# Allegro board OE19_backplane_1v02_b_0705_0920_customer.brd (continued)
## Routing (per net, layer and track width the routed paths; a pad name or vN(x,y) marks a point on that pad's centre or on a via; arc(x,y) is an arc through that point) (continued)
FM_BMC_SLED3_READY_N: length 72.1
  TOP w0.114: v1(203.01,30.38) 203.01,30.38 199.68,33.71 193.08,36.44 187.07,36.44 185.84,35.21 185.84,26.29 J8.F8
  IN1 w0.127: v1(203.01,30.38) 205.21,32.58 213.16,32.58 214.76,30.98 215.9,30.98 v1(216.16,31.24)
  BOTTOM w0.114: J10.H3 225.7,52.75 225.7,43.67 216.16,34.12 v1(216.16,31.24)
FM_BMC_SLED4_READY_N: length 225.1
  TOP w0.114: v1(31.77,68.45) 31.17,67.85 31.17,44.98 37.68,38.47 175.37,38.47 175.98,37.86 175.98,33.25 J8.K3
  BOTTOM w0.114: J11.H3 8.24,95.56 8.24,76.65 15.57,69.32 30.9,69.32 v1(31.77,68.45)
FM_BMC_SLED5_READY_N: length 109.6
  TOP w0.114: J12.H3 225.61,95.51 225.61,77.27 216.34,68 216.34,32.47 v1(215.32,31.45) ; v1(202.11,30.48) 201.79,30.8 201.79,31.23 199.53,33.48 193.02,36.18 187.18,36.18 186.11,35.1 186.11,30.23 J8.I8
  IN1 w0.127: v1(215.32,31.45) 214.95,31.45 213.36,33.05 204.68,33.05 v1(202.11,30.48)
FM_RMC_GPIO_0: length 450.7
  TOP w0.114: J9.D3 8.12,49.57 8.12,57.42 11.91,61.21 11.91,66.98 v1(13.87,68.94) ; v1(216.85,30.61) 216.85,68.12 225.88,77.16 225.88,90.18 J12.D3 ; J7.D3 226.02,6.48 226.02,9.93 225.56,10.38 225.56,12.7 225.15,13.11 224.35,13.11 216.84,20.62 v1(216.84,25.11) ; v1(226.77,75.2) 226.77,71.59 231.89,66.46 231.89,60.24 228.14,56.48 228.14,49.59 J10.D3 ; v1(204.43,31.12) 204.43,31.13 201.84,33.72 193.25,37.28 185.14,37.28 v1(184.91,37.05) 184.32,37.05 183.73,36.46 183.73,26.06 J8.F6
  IN1 w0.127: v1(204.43,31.12) 205.55,32.25 212.71,32.25 214.35,30.61 v1(216.85,30.61) ; v1(32.86,33.61) 32.86,34.02 37.35,38.52 179.56,38.52 181.02,37.05 v1(184.91,37.05)
  BOTTOM w0.114: J11.D3 7.8,90.4 7.8,74.39 10.37,71.83 10.97,71.83 v1(13.87,68.94) ; J9.D3 7.31,48.4 7.83,47.88 7.83,43.7 9.41,42.12 15.42,42.12 17.89,39.65 25.72,39.65 31.76,33.61 v1(32.86,33.61) ; v1(216.84,25.11) 216.84,26.2 217.62,26.98 217.62,34.61 226.24,43.23 226.24,47.69 J10.D3 ; J12.D3 226.97,91.25 227.91,90.32 227.91,84.22 226.9,83.22 226.9,75.33 v1(226.77,75.2)
FM_RMC_GPIO_1: length 388.3
  TOP w0.114: v1(6.19,56.37) 6.19,50.56 J9.E3 ; J7.E3 226.29,7.61 226.29,10.04 225.83,10.49 225.83,12.81 225.26,13.38 224.46,13.38 217.11,20.73 217.11,23.38 v1(218.18,24.44) ; J8.H6 181.75,29.19 181.75,30.21 181.74,30.22 181.74,34.15 v1(180.92,34.97) 180.61,35.28 180.61,35.9 181.28,36.56 182.62,36.56 183.87,37.82 193.35,37.82 202.6,33.99 205.98,30.61 205.98,30.34 v1(206.3,30.01) ; v1(226.3,74.77) 226.3,71.56 231.63,66.23 231.63,60.47 227.84,56.68 227.84,50.69 J10.E3
  IN1 w0.127: v1(206.3,30.01) 207.04,29.27 212.78,29.27 214.89,27.16 215.46,27.16 v1(218.18,24.44) ; v1(180.92,34.97) 180.61,35.29 180.61,35.78 179.08,37.3 38.22,37.3 34.67,33.75 v1(34.67,33.64)
  BOTTOM w0.114: J9.E3 8.1,48.65 8.1,43.93 9.58,42.44 15.62,42.44 18.15,39.91 25.94,39.91 31.74,34.11 34.2,34.11 v1(34.67,33.64) ; J12.E3 226.55,92.65 226.13,92.23 226.13,74.94 v1(226.3,74.77) ; v1(218.18,24.44) 219.17,25.43 219.17,34.21 228.05,43.1 228.05,48.7 J10.E3 ; v1(6.19,56.37) 6.19,56.99 6.86,57.66 8.19,57.66 8.4,57.74 13.18,62.53 13.18,67.45 6.31,74.32 6.31,92.01 J11.E3
FM_RMC_GPIO_2: length 391.6
  TOP w0.114: v1(7.86,58.12) 7.86,53.51 J9.G3 ; J10.G3 227.57,53.22 227.57,56.79 231.36,60.58 231.36,66.12 225.83,71.65 225.83,75.55 227.29,77.01 227.29,82.1 227.83,82.64 227.83,94.57 J12.G3 ; J7.G3 226.1,10.6 226.1,12.93 225.37,13.65 224.57,13.65 217.58,20.65 v1(217.58,23.11) ; v1(205.62,30.03) 205.34,30.32 205.34,30.87 202.44,33.76 193.3,37.55 183.98,37.55 182.73,36.3 181.39,36.3 181.11,36.02 v1(181.11,35.74) 181.11,35.44 182.01,34.54 182.01,30.33 J8.I6
  IN1 w0.127: v1(181.11,35.74) 179.22,37.63 164.55,37.63 164.53,37.65 38.01,37.65 34.14,33.78 v1(34.14,32.58) ; v1(217.58,23.11) 217.58,23.64 212.96,28.26 209.55,28.26 208.86,28.94 206.7,28.94 205.62,30.02 v1(205.62,30.03)
  BOTTOM w0.114: v1(217.58,23.11) 216.26,24.43 216.26,25.98 217.36,27.09 217.36,34.82 225.97,43.43 225.97,51.62 J10.G3 ; J9.G3 6.55,52.6 6.29,52.33 6.29,43.65 9.48,40.46 15,40.46 17.15,38.31 25.29,38.31 31.48,32.12 33.68,32.12 v1(34.14,32.58) ; J11.G3 6.05,94.55 6.05,74.21 12.23,68.03 12.23,61.95 8.78,58.51 v1(7.86,58.12)
FM_SLED1_PRSNT_N: length 85.8
  TOP w0.114: J7.B3 227.83,3.63 227.83,12.91 226.56,14.18 224.79,14.18 218.48,20.5 218.48,23.31 218.91,23.73 218.91,24.75 217.17,26.48 212.83,26.48 212.62,26.7 v1(212.37,26.7) R36.2
  IN1 w0.127: J8.B8 188.09,20.83 188.09,34.81 188.94,35.66 191.31,35.66 195.3,31.67 195.3,28.18 198.47,25.01 213.11,25.01 213.36,25.26 213.36,25.96 212.62,26.7 v1(212.37,26.7)
FM_SLED2_PRSNT_N: length 217.2
  TOP w0.114: J8.G3 177.78,27.61 177.78,34.45 v1(176.73,35.49) 176.73,36.48 177.98,37.73 181.65,37.73 v1(182.15,38.23) ; R35.2 199.91,29.79 199.04,30.65 v1(199.04,31.27)
  IN1 w0.127: v1(36.17,32.66) 36.17,33.17 39.01,36.01 176.32,36.01 176.73,35.59 v1(176.73,35.49) ; v1(199.04,31.27) 199.04,31.92 192.48,38.48 182.41,38.48 v1(182.15,38.23)
  BOTTOM w0.114: v1(36.17,32.66) 35.59,32.66 35.16,33.09 31.71,33.09 25.41,39.38 17.54,39.38 15.39,41.53 9.62,41.53 7.56,43.59 7.56,44.94 6.95,45.55 J9.B3
FM_SLED3_PRSNT_N: length 62.7
  TOP w0.114: J8.E8 186.9,24.3 187.58,24.98 187.58,26.53 188,26.95 188,33.7 189.95,35.64 192.92,35.64 197.63,33.69 200.06,31.26 v1(200.06,30.47) 200.92,29.61 R34.2
  IN1 w0.127: v1(218.57,33.71) 203.3,33.71 v1(200.06,30.47)
  BOTTOM w0.114: J10.B3 227.79,44.76 227.79,43.5 218.57,34.28 v1(218.57,33.71)
FM_SLED4_PRSNT_N: length 255.9
  TOP w0.114: v1(11,58.39) 11.94,57.45 11.94,43.11 v1(12.13,42.92) ; J8.J3 177.51,31.54 177.51,34.05 v1(176.97,34.59) 176.27,35.29 176.27,36.39 178.12,38.25 v1(181.34,38.25) ; v1(198.07,30.21) 198.33,30.21 198.89,29.65 R33.2
  IN1 w0.127: v1(176.97,34.59) 175.93,35.63 39.16,35.63 37.48,33.94 37.48,33.4 v1(37.32,33.24) ; v1(181.34,38.25) 181.83,37.76 182.46,37.76 182.85,38.15 192.34,38.15 198.07,32.43 v1(198.07,30.21)
  BOTTOM w0.114: v1(37.32,33.24) 35.92,33.24 34.7,34.46 31.85,34.46 26,40.31 18.43,40.31 15.83,42.92 v1(12.13,42.92) ; v1(11,58.39) 11,59.16 14.09,62.25 14.09,67.73 7.54,74.28 7.54,87.86 J11.B3
FM_SLED5_PRSNT_N: length 103.4
  TOP w0.114: R30.2 201.94,29.59 v1(201.08,30.45) 201.08,31.24 198.84,33.48 192.97,35.91 189.84,35.91 187.73,33.81 187.73,28.87 J8.H8 ; v1(218.63,32.76) 217.68,33.7 217.68,67.78 227.03,77.12 227.03,82.21 227.56,82.75 227.56,87.84 J12.B3
  IN1 w0.127: v1(218.63,32.76) 218.01,33.38 204,33.38 v1(201.08,30.45)
IRQ_RMC_ALERT_N: length 400.7
  TOP w0.114: J8.E6 184.15,25.08 184.15,36.23 v1(184.45,36.53) 185.33,36.53 185.66,36.86 193.16,36.86 201.53,33.4 204.02,30.91 v1(204.02,30.45) ; v1(6.85,57) 6.17,57 5.73,56.56 5.73,45.42 J9.A3 ; J7.A3 228.25,2.65 228.25,13.09 226.74,14.6 224.97,14.6 218.94,20.63 v1(218.94,22.71) ; J12.A3 226.61,86.71 226.61,77.29 217.26,67.95 217.26,32.29 218.09,31.47 v1(218.09,30.96)
  IN1 w0.127: v1(204.02,30.45) 204.97,30.45 205.88,31.35 212.99,31.35 214.21,30.14 217.26,30.14 v1(218.09,30.96) ; v1(184.45,36.53) 180.93,36.53 179.38,38.09 37.69,38.09 33.47,33.87 v1(33.47,32.61)
  BOTTOM w0.114: J10.A3 226.95,43.33 218.09,34.47 v1(218.09,30.96) 218.04,30.92 218.04,26.7 217.45,26.11 217.45,24.21 v1(218.94,22.71) ; v1(6.85,57) 7.07,57.21 8.2,57.21 8.63,57.39 13.64,62.39 13.64,67.59 6.95,74.28 J11.A3 ; v1(33.47,32.61) 31.59,32.61 25.43,38.77 17.44,38.77 15.14,41.07 9.48,41.07 6.95,43.6 J9.A3
LAN_SLED1_MDIN0: length 53
  IN2 w0.114: J8.C10 191.39,20.55 196.73,20.55 205.38,20.36 217.8,15.19 227.62,15 229.06,14.38 230.16,13.28 230.16,2.4 230.3,2.26 230.46,2.26 J7.B1
LAN_SLED1_MDIN1: length 53.7
  IN2 w0.114: J7.E1 231.44,6.46 232.05,6.46 232.26,6.55 232.31,6.6 232.46,6.95 232.49,7.94 232.3,8.13 232.31,8.48 232.5,8.66 232.51,9 232.33,9.2 232.34,9.54 232.53,9.72 232.54,10.07 232.36,10.26 232.36,10.6 232.56,10.79 232.57,11.13 232.38,11.32 232.39,11.67 232.58,11.85 232.59,12.24 232.59,12.79 232.37,13.14 232.02,13.2 231.83,13.49 231.9,13.83 231.53,14.39 231,14.61 230.69,14.48 230.37,14.61 230.25,14.92 227.88,15.9 220.35,15.97 218.06,16.91 217.74,16.77 217.42,16.91 217.28,17.23 216.97,17.37 216.64,17.23 216.32,17.36 216.18,17.69 206.67,21.63 193.13,24.32 191.39,24.32 J8.E10
LAN_SLED1_MDIN2: length 47.1
  BOTTOM w0.099: J8.B9 189.42,19.21 189.73,19.21 190.08,18.86 190.08,17.98 190.12,17.87 190.27,17.72 190.43,17.65 192.12,17.65 194.52,18.65 205.17,18.82 228.81,14.12 229.54,13.82 229.88,13.48 230.13,12.88 230.13,10.79 230.29,10.63 230.43,10.63 J7.H1
LAN_SLED1_MDIN3: length 48.4
  IN2 w0.114: J8.E9 189.39,23.45 189.73,23.45 190.11,23.06 190.11,17.99 190.45,17.65 191.16,17.65 194.22,18.92 195.96,19.25 205.26,19.02 217.85,13.81 219.29,13.81 227.24,13.74 227.78,13.52 228.16,13.14 228.16,12.1 228.3,11.96 228.46,11.96 J7.I2
LAN_SLED1_MDIP0: length 53
  IN2 w0.114: J8.B10 191.39,20.12 196.72,20.12 205.29,19.94 217.71,14.77 227.53,14.57 228.82,14.02 229.74,13.1 229.74,2.22 230.12,1.84 230.46,1.84 J7.A1
LAN_SLED1_MDIP1: length 53.6
  IN2 w0.114: J8.F10 191.39,24.75 193.17,24.75 199.98,23.39 206.79,22.04 220.43,16.39 227.97,16.32 231.81,14.73 233.02,12.92 233.02,12.23 232.89,6.86 232.67,6.36 232.5,6.19 232.14,6.04 231.44,6.04 J7.D1
LAN_SLED1_MDIP2: length 47.1
  BOTTOM w0.099: J8.A9 189.42,18.86 189.58,18.86 189.72,18.72 189.72,17.91 189.82,17.67 190.07,17.42 190.36,17.3 192.19,17.3 194.59,18.29 205.14,18.47 228.71,13.78 229.34,13.52 229.58,13.28 229.77,12.81 229.77,10.64 230.14,10.27 230.43,10.27 J7.G1
LAN_SLED1_MDIP3: length 48.5
  IN2 w0.114: J8.D9 189.39,23.02 189.55,23.02 189.69,22.88 189.69,17.81 190.27,17.22 191.24,17.22 194.35,18.51 195.99,18.82 205.17,18.6 217.76,13.38 219.29,13.38 227.15,13.32 227.54,13.16 227.74,12.96 227.74,11.92 228.12,11.54 228.46,11.54 J7.H2
LAN_SLED2_MDIN0: length 172.5
  BOTTOM w0.099: J9.B1 11.51,45.04 11.97,45.04 14.18,44.83 25.69,41.71 37.21,34.27 41.45,34.39 49.09,33.94 62.97,34.36 65.1,34.21 71.59,34.59 84.85,34.49 99.57,33.55 120.69,34.59 131.16,33.79 140.67,34.61 154.56,33.44 157.52,33.55 160.61,33.67 162.54,32.65 171.68,19.46 172.16,19.21 172.38,19.21 J8.B1
LAN_SLED2_MDIN1: length 172.1
  BOTTOM w0.099: J9.E1 11.47,49.28 11.86,49.28 12.19,49.09 13.21,47.41 13.77,46.75 14.99,45.69 26.01,42.67 37.49,35.26 42.16,35.4 46.1,35.17 58.97,35.56 60.34,35.53 65.11,35.2 71.57,35.58 84.88,35.48 99.58,34.54 120.7,35.57 131.15,34.78 140.67,35.6 154.58,34.42 160.79,34.67 163.12,33.66 169.41,24.6 171.68,23.41 172.38,23.41 J8.E1
LAN_SLED2_MDIN2: length 185.6
  BOTTOM w0.099: J8.C2 174.38,20.51 174.24,20.51 174.08,20.67 174.08,33.93 173.99,34.23 173.46,34.88 172.89,35.18 170.89,35.38 166.25,35.19 162.83,35.73 154.6,35.41 140.67,36.59 131.15,35.77 120.71,36.56 99.58,35.53 84.92,36.46 84.91,36.46 71.56,36.56 71.54,36.56 65.11,36.19 59.64,36.57 46.07,36.16 42.17,36.39 37.76,36.25 26.31,43.65 15.75,46.54 14.13,47.91 12.55,51.27 12.55,52.49 12.28,53.12 11.93,53.48 11.47,53.48 J9.H1
LAN_SLED2_MDIN3: length 202.1
  BOTTOM w0.099: J8.F2 175.42,24.71 175.56,24.71 175.72,24.87 175.72,35.26 175.62,35.71 175.19,36.37 174.4,36.52 174.22,36.4 173.93,36.46 173.81,36.63 173.52,36.69 173.34,36.57 173.05,36.63 172.93,36.8 172.31,36.92 171.67,36.87 171.55,36.74 171.26,36.71 171.12,36.83 170.82,36.81 170.7,36.67 170.4,36.65 170.26,36.77 169.84,36.74 169.71,36.59 169.41,36.57 169.26,36.69 168.96,36.67 168.84,36.52 168.54,36.5 168.39,36.63 168.09,36.61 167.96,36.46 167.67,36.44 167.52,36.56 167.12,36.53 165.45,36.47 165.29,36.29 164.99,36.28 164.82,36.44 164.52,36.43 164.36,36.26 164.06,36.25 163.89,36.41 154.62,36.04 140.67,37.22 131.4,36.43 121.05,37.21 99.59,36.16 95.91,36.39 84.94,37.09 71.53,37.2 65.12,36.82 59.35,37.22 46.21,36.83 42.22,37.06 38.35,37.01 26.21,44.68 23,46.26 22.42,46.95 22.2,47.68 21.97,49.96 22.17,52.27 22.27,58.17 22,59.14 21.13,60.61 20.02,61.3 18.74,61.38 18.58,61.24 18.29,61.26 18.14,61.42 17.85,61.44 17.68,61.3 17.39,61.32 17.25,61.48 16.55,61.53 16.15,61.24 16.12,61.02 15.88,60.85 15.66,60.88 15.42,60.71 15.38,60.49 15.14,60.32 14.92,60.36 14.2,59.84 13.85,59.02 13.36,58.7 13.32,58.48 13.07,58.32 12.85,58.36 12.6,58.2 12.56,57.98 12.31,57.82 12.09,57.86 11.84,57.7 11.79,57.48 11.55,57.31 11.32,57.36 10.99,57.14 10.65,57 10.58,56.83 10.3,56.71 10.13,56.78 9.86,56.67 9.78,56.5 9.51,56.38 9.34,56.45 8.28,56.02 8.13,55.65 8.13,54.94 8.29,54.78 8.43,54.78 J9.I2
LAN_SLED2_MDIP0: length 172.4
  BOTTOM w0.099: J9.A1 11.44,44.69 11.95,44.69 14.11,44.48 25.54,41.38 37.11,33.91 41.44,34.04 49.09,33.59 62.96,34.01 65.1,33.86 71.6,34.24 84.84,34.14 99.57,33.2 120.68,34.23 131.16,33.44 140.67,34.25 147.61,33.67 154.55,33.08 160.52,33.32 162.3,32.38 171.44,19.19 172.07,18.86 172.38,18.86 J8.A1
LAN_SLED2_MDIP1: length 172.1
  BOTTOM w0.099: J8.D1 172.38,23.06 171.59,23.06 169.17,24.33 162.89,33.37 160.72,34.31 154.57,34.07 140.67,35.24 131.15,34.43 120.69,35.22 99.58,34.19 84.87,35.12 71.58,35.23 65.11,34.85 60.32,35.18 58.97,35.2 46.09,34.82 42.15,35.05 37.39,34.9 25.86,42.35 14.82,45.37 13.52,46.5 12.92,47.2 11.94,48.83 11.77,48.92 11.47,48.92 J9.D1
LAN_SLED2_MDIP2: length 185.6
  BOTTOM w0.099: J9.G1 11.47,53.12 11.78,53.12 11.98,52.92 12.19,52.42 12.19,51.19 13.84,47.69 15.59,46.22 26.16,43.33 37.66,35.9 42.17,36.04 46.06,35.81 59.63,36.21 65.11,35.83 71.55,36.21 84.91,36.11 92.23,35.64 99.58,35.17 120.71,36.21 131.15,35.42 131.18,35.42 140.67,36.23 154.59,35.06 162.81,35.38 166.23,34.84 170.88,35.02 172.79,34.84 173.23,34.6 173.67,34.06 173.72,33.88 173.72,20.52 174.09,20.16 174.38,20.16 J8.B2
LAN_SLED2_MDIP3: length 202.2
  BOTTOM w0.099: J8.E2 175.42,24.36 175.71,24.36 176.08,24.72 176.08,35.29 175.95,35.85 175.41,36.69 174.47,36.87 174.47,36.87 172.33,37.28 167.09,36.89 154.62,36.4 140.67,37.58 131.4,36.78 121.06,37.56 99.59,36.51 92.27,36.98 84.95,37.45 78.24,37.5 78.24,37.5 71.52,37.55 65.12,37.18 59.35,37.57 46.22,37.18 42.23,37.41 38.45,37.36 26.39,44.99 23.22,46.55 22.73,47.12 22.55,47.74 22.33,49.96 22.53,52.25 22.63,58.22 22.33,59.28 21.39,60.87 20.13,61.64 16.45,61.89 13.92,60.07 13.81,59.82 13.57,59.26 11.25,57.73 11.25,57.74 10.83,57.46 10.52,57.33 9.2,56.78 9.2,56.78 8.01,56.29 7.77,55.72 7.77,54.79 8.14,54.42 8.43,54.42 J9.H2
LAN_SLED3_MDIN0: length 48.9
  IN2 w0.114: J10.B1 231.44,45.11 232.13,45.11 232.66,44.58 232.66,44 231.74,41.76 231.31,41.34 230.89,40.92 228.04,39.73 221.5,39.23 220.58,38.82 216.4,34.77 213.57,33.58 195.13,33.39 193.73,32.81 191.48,32.81 J8.K10
LAN_SLED3_MDIN1: length 58.6
  IN2 w0.114: J10.E1 231.44,49.31 231.98,49.31 234.43,48.3 235.23,47.5 235.23,43.36 234.96,42.74 231,39.04 228.63,38.15 222.34,38.01 221.07,37.49 217.02,33.64 213.83,32.33 199.18,32.12 196.5,30.99 195.27,29.77 192.18,28.48 191.35,28.48 J8.H10
LAN_SLED3_MDIN2: length 62.9
  IN2 w0.114: J10.H1 230.46,53.51 230.12,53.51 229.74,53.13 229.74,44.02 229.17,42.65 227.49,41.96 224.44,41.68 222.12,41.56 222.01,41.54 221.9,41.51 220.08,40.76 215.3,36.13 213.39,35.33 195.6,35.22 191.32,36.07 190.5,36.07 189.69,35.25 189.69,27.79 189.55,27.65 189.39,27.65 J8.H9
LAN_SLED3_MDIN3: length 60.5
  IN2 w0.114: J10.I2 228.46,54.81 228.12,54.81 227.74,54.43 227.74,44.01 227.12,43.4 225.46,43.24 222.07,42.9 221.89,42.87 219.32,41.8 214.58,37.19 213.1,36.58 195.92,36.76 191.89,37.32 189.99,37.32 188.62,36.75 188.39,36.52 187.69,34.83 187.69,31.81 188.07,31.42 188.41,31.42 J8.J9
LAN_SLED3_MDIP0: length 48.9
  IN2 w0.114: J8.L10 191.3,33.24 191.62,33.24 191.91,33.53 192.23,33.53 192.52,33.24 193.64,33.24 195.05,33.82 213.49,34.01 216.16,35.13 220.34,39.18 221.39,39.65 222.06,39.7 222.33,40.02 222.65,40.04 222.96,39.77 223.28,39.8 223.55,40.11 223.86,40.14 224.17,39.87 224.49,39.89 224.76,40.2 225.08,40.23 225.39,39.96 225.71,39.98 225.98,40.3 226.29,40.32 226.61,40.05 227.94,40.15 230.65,41.28 231.37,42.01 231.63,42.61 231.47,43 231.59,43.29 231.97,43.45 232.24,44.09 232.24,44.4 231.95,44.69 231.44,44.69 J10.A1
LAN_SLED3_MDIP1: length 58.6
  IN2 w0.114: J8.I10 191.42,28.91 192.09,28.91 195.03,30.13 196.26,31.35 199.09,32.55 213.74,32.76 216.79,34 220.84,37.85 222.25,38.43 228.55,38.58 230.77,39.41 231.44,40.03 231.44,40.28 231.7,40.52 231.94,40.51 232.2,40.74 232.2,40.99 232.45,41.22 232.7,41.22 232.95,41.45 232.96,41.7 233.21,41.93 233.46,41.92 233.71,42.16 233.72,42.41 233.97,42.64 234.22,42.63 234.61,42.99 234.8,43.45 234.8,43.75 234.59,43.96 234.59,44.3 234.8,44.51 234.8,44.86 234.59,45.06 234.59,45.41 234.8,45.61 234.8,45.96 234.59,46.17 234.59,46.51 234.8,46.72 234.8,47.32 234.18,47.94 233.91,48.05 233.67,47.95 233.36,48.09 233.26,48.32 232.94,48.45 232.71,48.36 232.39,48.49 232.29,48.72 231.9,48.89 231.44,48.89 J10.D1
LAN_SLED3_MDIP2: length 62.9
  IN2 w0.114: J10.G1 230.46,53.09 230.3,53.09 230.16,52.95 230.16,43.93 229.5,42.33 227.59,41.54 224.47,41.25 222.18,41.14 222.03,41.11 220.32,40.39 215.54,35.77 213.56,34.94 213.56,34.94 213.48,34.9 195.56,34.79 191.27,35.64 190.68,35.64 190.11,35.07 190.11,27.61 189.73,27.22 189.39,27.22 J8.G9
LAN_SLED3_MDIP3: length 60.5
  IN2 w0.114: J10.H2 228.46,54.39 228.3,54.39 228.16,54.25 228.16,43.84 227.32,42.99 226.86,42.95 226.73,42.78 226.38,42.74 226.22,42.88 225.68,42.83 225.55,42.68 225.21,42.64 225.06,42.77 224.71,42.73 224.59,42.58 224.25,42.55 224.09,42.67 223.75,42.64 223.63,42.49 223.29,42.45 223.13,42.58 222.14,42.48 222.02,42.46 219.56,41.44 214.82,36.82 213.19,36.16 195.89,36.33 195.45,36.39 195.26,36.25 194.92,36.29 194.77,36.49 194.43,36.53 194.24,36.39 193.9,36.44 193.75,36.63 193.41,36.68 193.24,36.55 192.87,36.6 192.74,36.77 191.86,36.89 190.08,36.89 189.77,36.77 189.69,36.57 189.37,36.43 189.17,36.52 188.86,36.39 188.75,36.28 188.52,35.72 188.63,35.46 188.5,35.14 188.23,35.03 188.11,34.75 188.11,33.68 188.31,33.49 188.31,33.14 188.11,32.95 188.11,31.99 188.25,31.85 188.41,31.85 J8.K9
LAN_SLED4_MDIN0: length 207
  IN2 w0.114: J11.B1 11.44,87.96 12.14,87.96 12.56,87.67 13.14,86.11 12.57,79.09 13.19,66.95 13.31,66.84 13.33,66.5 13.22,66.38 13.25,65.9 14.13,60.67 13.99,59.72 13.01,55.57 13.04,50.5 14.45,46.91 17.05,44.17 39.31,34.05 65.5,33.71 111.8,34 117.74,33.55 155.14,34.23 161.4,33.41 167.59,30.35 170.72,28.11 171.83,27.65 172.41,27.65 J8.H1
LAN_SLED4_MDIN1: length 203.3
  IN2 w0.114: J11.E1 11.44,92.16 11.9,92.16 12.34,91.98 13.23,91.08 15.04,86.73 16.12,74.67 21.41,61.24 21.56,60.6 22.25,49.44 22.41,49.3 22.43,48.96 22.29,48.81 22.36,47.77 23.2,45.95 34.76,37.79 39.41,35.6 65.51,35.27 108.17,35.53 117.78,34.8 155.21,35.49 166.04,34.06 171.37,31.85 172.41,31.85 J8.K1
LAN_SLED4_MDIN2: length 212.9
  IN2 w0.114: J11.H1 11.44,96.36 11.94,96.36 12.37,95.93 12.57,95.45 12.57,94.33 13.09,93.08 15.98,90.19 16.11,89.93 17.72,75.06 19.36,72.12 28.65,64.95 28.87,64.51 29.2,49.11 29.62,47.22 31.26,43.5 35.79,39.16 37.76,37.81 40.69,36.87 65.52,36.55 107.81,36.81 117.81,36.06 155.28,36.74 167.83,35.08 172.39,35.28 173.57,34.79 174.11,33.98 174.11,29.09 174.25,28.95 174.41,28.95 J8.I2
LAN_SLED4_MDIN3: length 232.6
  IN2 w0.114: J11.I2 8.46,97.66 8.28,97.66 8.16,97.78 8.16,98.69 8.29,98.82 8.35,98.88 8.35,99.22 8.29,99.28 8.16,99.4 8.16,99.63 8.24,99.8 8.85,100.34 9.05,100.33 9.31,100.55 9.32,100.76 9.58,100.98 9.78,100.97 10.04,101.2 10.05,101.4 10.51,101.81 11.23,102.08 11.41,101.99 11.74,102.12 11.82,102.3 12.14,102.42 12.32,102.34 12.64,102.46 12.73,102.64 13.11,102.79 13.58,102.82 13.8,102.63 14.14,102.66 14.33,102.88 14.68,102.91 14.9,102.72 15.24,102.74 15.43,102.97 15.77,102.99 16,102.8 16.34,102.83 16.53,103.05 16.87,103.08 17.09,102.89 17.44,102.91 17.63,103.14 17.92,103.16 18.96,102.95 19.26,102.79 19.34,102.54 19.65,102.38 19.9,102.46 20.2,102.31 20.28,102.05 20.59,101.9 20.84,101.98 21.14,101.82 21.78,100.81 21.82,99.89 21.64,99.7 21.65,99.36 21.85,99.17 22.12,92.25 22.12,92.19 19.21,78.98 19.24,75.18 19.65,73.96 21.09,72.02 26.54,68.26 29.52,65.6 30.21,64.11 30.39,56.24 30.57,48.37 31.18,46.96 32.01,46.17 37.24,39.19 38.82,38.57 38.91,38.37 39.23,38.24 39.42,38.33 40.44,37.93 41.37,37.75 65.52,37.44 101.21,37.66 101.37,37.64 109.1,37.79 109.12,37.79 116.81,37.1 159.87,37.62 166.96,36.99 167.19,36.72 167.44,36.7 167.72,36.93 168.06,36.9 168.24,36.69 168.58,36.66 168.79,36.83 169.13,36.8 169.3,36.59 169.65,36.56 169.86,36.74 170.19,36.71 170.37,36.5 170.71,36.47 170.92,36.64 171.26,36.61 171.44,36.4 171.78,36.37 171.99,36.55 174.17,36.35 175.47,35.81 175.69,35.29 175.69,33.29 175.55,33.15 175.39,33.15 J8.L2
LAN_SLED4_MDIP0: length 206.9
  IN2 w0.114: J11.A1 11.44,87.54 12.01,87.54 12.21,87.4 12.7,86.05 12.15,79.1 12.82,65.86 13.7,60.66 13.57,59.8 12.59,55.62 12.62,50.42 14.08,46.68 16.8,43.81 39.22,33.63 65.5,33.29 111.78,33.57 117.73,33.12 155.12,33.81 156.66,33.6 161.27,32.99 167.37,29.98 170.51,27.73 171.74,27.22 172.41,27.22 J8.G1
LAN_SLED4_MDIP1: length 203.2
  IN2 w0.114: J8.J1 172.41,31.42 171.29,31.42 165.93,33.64 155.19,35.06 117.76,34.38 108.15,35.1 65.51,34.84 39.31,35.18 34.55,37.42 22.86,45.67 21.94,47.67 21.86,48.96 21.13,60.54 21,61.12 15.7,74.57 14.62,86.63 12.87,90.84 12.09,91.62 11.81,91.74 11.44,91.74 J11.D1
LAN_SLED4_MDIP2: length 212.9
  IN2 w0.114: J8.H2 174.41,28.52 174.07,28.52 173.69,28.91 173.69,33.85 173.29,34.45 172.32,34.85 167.82,34.66 155.26,36.32 117.8,35.63 107.79,36.38 65.52,36.12 40.62,36.44 37.57,37.42 35.52,38.83 30.9,43.25 29.21,47.09 28.78,49.06 28.45,64.4 28.31,64.67 19.04,71.84 17.31,74.93 15.69,89.81 15.64,89.93 15.63,89.94 12.79,92.78 12.73,92.84 12.15,94.25 12.15,95.36 12.01,95.69 11.76,95.94 11.44,95.94 J11.G1
LAN_SLED4_MDIP3: length 232.6
  IN2 w0.114: J11.H2 8.46,97.24 8.1,97.24 7.74,97.6 7.74,99.71 7.88,100.06 10.29,102.18 13.02,103.21 17.95,103.59 19.11,103.35 21.43,102.15 22.21,100.94 22.46,94.44 22.46,94.44 22.55,92.24 22.54,92.13 19.64,78.93 19.67,75.25 20.03,74.16 21.39,72.33 26.81,68.6 29.87,65.86 30.63,64.2 30.99,48.46 31.54,47.21 32.33,46.45 37.51,39.54 40.56,38.34 41.42,38.17 65.52,37.87 101.23,38.08 101.38,38.07 109.11,38.21 109.13,38.21 109.15,38.21 116.82,37.53 159.89,38.05 166.99,37.42 174.27,36.77 175.8,36.14 176.11,35.37 176.11,33.11 175.73,32.72 175.39,32.72 J8.K2
LAN_SLED5_MDIN0: length 92.6
  IN2 w0.114: J12.B1 230.46,87.96 230.12,87.96 229.74,87.58 229.74,86.7 229.69,86.58 227.36,84.25 219.02,64.12 217.94,58.68 216.82,43.21 215.37,39.7 214.02,38.38 212.95,37.95 205.35,37.95 197.87,37.99 191.96,38.57 185.51,38.57 183.61,37.79 182.16,36.33 181.69,35.19 181.69,31.99 181.55,31.85 181.39,31.85 J8.K5
LAN_SLED5_MDIN1: length 121.6
  BOTTOM w0.099: J12.E1 231.47,92.13 231.61,92.13 231.95,92.46 232.04,93.55 231.87,93.76 231.89,94.06 232.1,94.24 232.13,94.53 231.95,94.74 231.98,95.04 232.19,95.22 232.21,95.52 232.04,95.73 232.06,96.02 232.27,96.2 232.3,96.5 232.12,96.71 232.15,97.01 232.36,97.19 232.43,97.97 232.15,98.54 231.95,98.61 231.82,98.88 231.89,99.08 231.69,99.5 231.26,100 230.99,100.18 230.76,100.14 230.51,100.31 230.47,100.53 230.22,100.7 230,100.65 229.75,100.82 229.71,101.04 229.18,101.4 224.36,101.85 220.09,101.5 218.8,100.38 217.17,96.66 217.04,41.15 216.55,40.14 214.86,38.32 210.8,37.51 189.57,37.73 186.05,36.62 185.65,36.33 184.13,34.34 184.08,34.17 184.08,33.12 183.71,32.76 183.42,32.76 J8.K6
LAN_SLED5_MDIN2: length 113.3
  BOTTOM w0.099: J8.K7 185.42,31.81 185.56,31.81 185.72,31.97 185.72,35.1 186.15,35.8 186.53,36.06 188.2,36.37 190.21,37.04 191.65,37.04 211.26,36.87 215.09,37.64 217.44,40.13 217.71,40.8 217.88,96.22 219.05,99.29 219.43,99.92 220.78,100.81 225.15,101.07 228.45,100.66 229.69,99.97 230.13,98.93 230.13,96.49 230.29,96.33 230.43,96.33 J12.H1
LAN_SLED5_MDIN3: length 104.9
  BOTTOM w0.099: J8.L8 187.42,33.11 187.56,33.11 187.72,33.27 187.72,34.07 188.18,34.81 188.66,35.23 190.14,35.89 190.93,36.05 211.39,35.81 213.45,36.22 213.45,36.22 215.51,36.63 218.58,39.89 219.17,41.42 218.79,65.14 219.11,96.4 219.93,98.76 220.36,99.21 221.81,99.77 225.43,99.9 227.32,99.42 227.81,99.03 228.13,98.38 228.13,97.79 228.29,97.63 228.43,97.63 J12.I2
LAN_SLED5_MDIP0: length 92.7
  IN2 w0.114: J8.J5 181.39,31.42 181.73,31.42 182.11,31.81 182.11,35.1 182.52,36.09 183.85,37.42 185.6,38.15 191.93,38.15 197.84,37.56 205.35,37.52 213.04,37.52 214.25,38.02 215.73,39.46 217.24,43.11 217.27,43.43 217.43,43.57 217.45,43.91 217.31,44.07 218.37,58.62 219.43,64 227.72,84.01 230.05,86.33 230.16,86.61 230.16,87.4 230.3,87.54 230.46,87.54 J12.A1
LAN_SLED5_MDIP1: length 121.7
  BOTTOM w0.099: J12.D1 231.47,91.77 231.76,91.77 232.29,92.31 232.79,98.03 231.99,99.69 231.5,100.26 231.18,100.48 229.31,101.74 224.36,102.21 219.95,101.84 218.5,100.6 216.81,96.74 216.69,41.23 216.26,40.34 214.68,38.64 210.77,37.86 189.52,38.08 189.47,38.07 185.89,36.94 185.4,36.59 183.82,34.51 183.72,34.23 183.72,33.27 183.56,33.11 183.42,33.11 J8.L6
LAN_SLED5_MDIP2: length 113.3
  BOTTOM w0.099: J8.J7 185.42,31.46 185.71,31.46 186.08,31.82 186.08,35 186.41,35.55 186.67,35.72 188.29,36.03 190.27,36.69 191.64,36.69 211.29,36.52 215.27,37.31 217.74,39.94 218.06,40.73 218.24,96.15 219.37,99.13 219.69,99.67 220.89,100.47 225.13,100.71 228.34,100.32 229.41,99.72 229.77,98.86 229.77,96.34 230.14,95.97 230.43,95.97 J12.G1
LAN_SLED5_MDIP3: length 105
  BOTTOM w0.099: J8.K8 187.42,32.76 187.71,32.76 188.08,33.12 188.08,33.97 188.45,34.58 188.85,34.93 190.25,35.55 190.96,35.7 211.42,35.46 215.69,36.3 218.89,39.7 219.53,41.36 219.15,65.14 219.46,96.34 220.24,98.57 220.56,98.91 221.88,99.42 225.39,99.54 227.16,99.1 227.53,98.8 227.77,98.3 227.77,97.64 228.14,97.27 228.43,97.27 J12.H2
PD_BBU_A0: length 17.2
  TOP w0.114: J7.H6 220.34,11.66 220.34,14.38 212.22,22.5 v1(212.22,22.53) 211.3,22.53 R31.2 R32.1
PD_SLED1_CHASSIS_INTRUSION: length 25.9
  TOP w0.114: R54.1 208.43,26.95 209.15,26.23 211.46,26.23 212.11,25.58 212.11,25.42 212.53,25 213.26,25 214.81,23.45 214.81,21.89 223.94,12.76 223.94,12.06 J7.H4
PD_SLED1_PRSNT_RETURN: length 74.1
  TOP w0.114: R41.1 166.44,34.13 169.29,31.29 169.29,27.55 172.12,24.72 173.61,24.72 173.83,24.5 173.83,22.35 174.44,21.74 175.75,21.74 176.29,21.2 176.29,20.88 176.78,20.4 187.18,20.4 188.54,21.77 191.5,21.77 193.94,24.21 v1(199.83,24.21)
  IN1 w0.127: v1(199.83,24.21) 210.32,24.21 210.68,23.86 210.68,22.39 211.71,21.36 214.26,21.36 215.18,20.44 215.18,17.56 220.29,12.45 J7.I6
PD_SLED2_CHASSIS_INTRUSION: length 16.7
  TOP w0.114: J9.H4 3.98,52.93 3.98,42.73 4.48,42.23 R55.1
PD_SLED2_PRSNT_RETURN: length 173.5
  TOP w0.114: v1(151.24,32.69) 151.24,33.28 152.23,34.28 R42.1
  BOTTOM w0.114: J9.I6 0.95,55.28 1.56,54.67 1.56,52.93 1.81,52.69 1.81,44.28 7.46,38.63 14.57,38.63 16.46,36.74 24.51,36.74 30.08,31.17 36.74,31.17 38.01,32.44 39.28,32.44 39.73,32.89 93.32,32.89 93.78,32.43 149.61,32.43 149.91,32.13 150.69,32.13 v1(151.24,32.69)
PD_SLED3_CHASSIS_INTRUSION: length 21.4
  TOP w0.114: J10.H4 224.02,54.83 224.02,55.43 219.34,60.11 219.34,65.77 223.7,70.12 R56.1
PD_SLED3_PRSNT_RETURN: length 94.7
  TOP w0.114: J10.I6 220.42,55.3 219.3,54.18 219.3,30.53 218.27,29.5 v1(215.48,29.5) ; v1(193.21,27.35) 193.1,27.24 190.65,27.24 190.29,26.89 190.29,26.63 189.65,26 188.65,26 187.88,25.23 187.88,23.82 187.22,23.15 182.28,23.15 181.79,23.64 181.79,24.21 181.44,24.56 176.59,24.56 176.29,24.86 176.29,25.23 175.51,26.01 174.38,26.01 173.87,26.51 173.87,28.57 173.53,28.91 172.22,28.91 170.83,30.3 170.83,33.23 167.49,36.57 R43.1
  IN2 w0.127: v1(193.21,27.35) 193.67,27.35 194.95,28.63 204.28,28.63 204.87,29.23 206.36,29.23 208.43,27.16 209.94,27.16 212.28,29.5 v1(215.48,29.5)
PD_SLED4_CHASSIS_INTRUSION: length 16.4
  TOP w0.114: R57.1 6.41,82.33 5.9,82.84 5.9,95.8 J11.H4
PD_SLED4_PRSNT_RETURN: length 213.4
  TOP w0.114: v1(149.97,32.86) 150.12,32.86 152.93,35.67 R44.1
  IN2 w0.127: v1(149.97,32.86) 149.28,32.16 117,32.16 116.81,32.35 51.63,32.35 51.44,32.54 37.23,32.54 35.43,34.34 28.84,34.34 24.62,38.56 15.19,38.56 10.19,43.56 10.19,58.6 11.68,60.09 11.68,66.36 8.18,69.86 8.18,83.2 5.22,86.16 2.66,86.16 1.92,86.91 1.92,97.28 1.05,98.15 J11.I6
PD_SLED5_CHASSIS_INTRUSION: length 17
  TOP w0.114: R58.1 224.54,82.28 223.89,82.93 223.89,95.69 J12.H4
PD_SLED5_PRSNT_RETURN: length 136.7
  TOP w0.114: R45.1 166.08,35.5 169.71,31.87 169.71,28.15 171.91,25.96 173.32,25.96 174.22,25.05 174.22,23.27 174.43,23.06 175.29,23.06 176.56,21.79 187.32,21.79 188.16,22.63 188.16,24.61 188.28,24.73 189.15,24.73 189.51,25.08 189.51,25.31 190.2,26.01 194.2,26.01 v1(194.44,26.26)
  BOTTOM w0.114: J12.I6 221.12,98.15 221.68,97.58 221.68,87.37 225.09,83.96 225.09,72.06 219.83,66.8 219.83,62.72 220.22,62.33 220.22,39.87 213.88,33.54 199.21,33.54 196.9,31.23 196.9,28.71 v1(194.44,26.26)
SB_SLED1_ADDR_0: length 41.2
  TOP w0.114: R2298.1 R2297.2 215.03,27.95 v1(215.32,27.95) 216.84,27.95 220.4,24.38 220.4,20.51 225.36,15.55 228.13,15.55 230.22,13.47 230.22,3.92 J7.B2
SB_SLED1_ADDR_1: length 38.5
  TOP w0.114: R13.2 R21.1 212.11,29.74 214.37,27.48 v1(216.64,27.48) 216.92,27.48 220.13,24.27 220.13,20.4 225.25,15.29 228.02,15.29 229.95,13.36 229.95,5.05 J7.C2
SB_SLED1_ADDR_2: length 34.4
  TOP w0.114: R24.1 R15.2 213.15,27.71 213.84,27.02 217.01,27.02 219.67,24.36 v1(219.67,20.93) 219.67,20.49 225.14,15.02 227.78,15.02 229.69,13.12 229.69,7.59 J7.E2
SB_SLED2_ADDR_0: length 22.6
  TOP w0.114: J9.B2 10.05,46.6 10.05,47.63 10.21,47.79 10.21,50.21 10.22,50.21 10.22,58.39 10.76,58.93 11.51,58.93 11.65,58.79 v1(11.76,58.79) 11.88,58.9 13.71,58.9 R8.2 R9.1
SB_SLED2_ADDR_1: length 20.1
  TOP w0.114: R1.2 R19.1 14.73,61.48 v1(14.6,61.35) 14.73,61.21 14.73,60.64 13.34,59.25 10.7,59.25 9.95,58.5 9.95,50.32 9.95,50.32 9.95,47.9 J9.C2
SB_SLED2_ADDR_2: length 16.2
  TOP w0.114: J9.E2 9.68,50.43 9.68,58.61 10.68,59.61 12.31,59.61 v1(12.97,60.26) 13.72,61.01 R22.1 R14.2
SB_SLED3_ADDR_0: length 28.6
  TOP w0.114: J10.B2 230.22,46.77 230.22,56.33 233.61,59.73 233.61,68.74 v1(233.71,68.83) 233.71,69.49 233.09,70.11 233.09,70.83 ; 233.09,70.83 R11.1 ; 233.09,70.83 R10.2
SB_SLED3_ADDR_1: length 27.3
  TOP w0.114: J10.C2 229.95,47.9 229.95,56.54 233.34,59.94 233.34,67.88 232.05,69.17 v1(232.05,70.1) R12.2 R20.1
SB_SLED3_ADDR_2: length 25.1
  TOP w0.114: J10.E2 229.68,50.43 229.68,56.65 233.08,60.05 233.08,67.38 v1(232.49,67.97) 230.02,70.44 R2.2 R23.1
SB_SLED4_ADDR_0: length 9.2
  TOP w0.114: J11.B2 8.34,87.74 8.34,83.35 v1(9.53,82.16) R3.2 R7.1
SB_SLED4_ADDR_1: length 10.9
  TOP w0.114: J11.C2 9.78,88.92 9.78,84.12 v1(11.56,82.35) R26.1 R18.2
SB_SLED4_ADDR_2: length 14.6
  TOP w0.114: J11.E2 10.16,91.34 10.16,85.41 v1(13.59,81.98) R6.2 R28.1
SB_SLED5_ADDR_0: length 9.1
  TOP w0.114: R17.1 R16.2 v1(228.22,81.66) 228.22,87.62 J12.B2
SB_SLED5_ADDR_1: length 10.8
  TOP w0.114: R4.2 R25.1 v1(230.25,81.61) 230.25,83.9 229.64,84.51 229.64,89.06 J12.C2
SB_SLED5_ADDR_2: length 14.4
  TOP w0.114: J12.E2 230.06,91.44 230.06,85.59 232.28,83.36 v1(232.28,81.79) R5.2 R27.1
SMB_3UBP_TEMP_SCL: length 6.3
  TOP w0.114: 35.45,23.31 R1123.1 38.25,21.87 38.91,21.22 U31.2
SMB_3UBP_TEMP_SDA: length 4.8
  TOP w0.114: 35.38,19.35 R1122.1 36.25,20.75 36.63,21.14 37.52,21.14 37.64,21.02 U31.1
SMB_BBU_ALERT_N: length 56.8
  TOP w0.114: v1(206.26,26.75) 206.26,24.98 206.26,24.14 209.79,20.6 R38.1 211.2,21.4 R37.2
  IN1 w0.127: J8.A7 183.68,19.56 183.68,34.61 186.79,37.72 192.16,37.72 197.36,32.53 197.36,29.09 199.17,27.27 205.74,27.27 v1(206.26,26.75)
SMB_BBU_ALERT_R_N: length 23.5
  TOP w0.114: R38.2 213.57,20.6 215.52,18.65 215.52,13.82 v1(215.6,13.74)
  BOTTOM w0.114: v1(215.6,13.74) 215.81,13.53 221.39,13.53 222.18,12.74 222.18,8.08 J7.E6
SMB_PMBUS_BBU_SCL: length 27.9
  TOP w0.114: J7.B6 222,3.7 222,13.82 213.98,21.84 213.98,22.9 v1(212.71,24.17) R39.2
SMB_PMBUS_BBU_SDA: length 25.3
  TOP w0.114: R40.2 211.4,24.66 v1(213.51,22.56) 213.51,21.75 221.61,13.65 221.61,4.71 J7.C6
SMB_PMBUS_SCL: length 44.5
  TOP w0.114: v1(208.91,25.81) 209.04,25.68 R39.1
  IN1 w0.127: v1(208.91,25.81) 198.74,25.81 196.06,28.5 196.06,31.99 191.63,36.42 187.32,36.42 186.15,35.25 186.15,24.58 185.85,24.28 185.85,23.49 J8.D7
SMB_PMBUS_SDA: length 44.2
  TOP w0.114: v1(207.48,26.28) 209.1,24.66 R40.1
  IN1 w0.127: J8.E7 185.72,24.76 185.72,35.43 187.14,36.86 191.81,36.86 196.49,32.17 196.49,28.68 198.89,26.28 v1(207.48,26.28)
SMB_SLED_BUF_SCL: length 406.4
  TOP w0.114: R52.2 166.57,30.17 v1(168.4,28.35) 168.4,24.59 172.5,20.49 173.43,20.49 173.72,20.2 173.72,18.26 174.47,17.51 191.7,17.51 192.3,18.12 v1(212.04,18.12) 212.77,17.38 v1(212.77,13.44)
  IN1 w0.127: v1(38.94,33.06) 40.56,34.68 145.51,34.68 151.54,28.65 168.09,28.65 v1(168.4,28.35)
  IN2 w0.127: v1(212.77,13.44) 212.77,11.92 214.3,10.4 221.97,10.4 222.62,9.75 J7.G5
  BOTTOM w0.114: J11.G5 3.14,95.45 3.65,94.94 3.65,75.34 11.6,67.4 11.6,62.42 9.43,60.25 4.82,58.34 2.32,55.85 2.32,53.23 J9.G5 2.95,52.58 3.63,51.9 3.63,43.86 8.05,39.44 14.84,39.44 16.91,37.37 24.46,37.37 30.36,31.47 36.61,31.47 37.89,32.76 38.63,32.76 v1(38.94,33.06) ; J12.G5 223.04,95.45 223.6,94.89 223.6,86.39 225.48,84.52 225.48,72.52 231.6,66.39 231.6,62.17 226.47,57.04 223.19,57.04 222.13,55.98 222.13,53.42 J10.G5 223.1,52.6 223.69,52.01 223.69,42.73 214,33.04 214,31.45 213.88,31.34 212.21,31.34 212.09,31.22 212.09,30.8 212.21,30.69 213.88,30.69 214,30.57 214,30.15 213.88,30.04 212.21,30.04 212.09,29.92 212.09,29.5 212.21,29.39 213.88,29.39 214.07,29.2 214.07,20.76 212.04,18.73 v1(212.04,18.12)
SMB_SLED_BUF_SCL_R: length 5.1
  TOP w0.114: R52.1 R50.2 164.78,29.1 164.45,29.43 U118.2
SMB_SLED_BUF_SDA: length 403.3
  TOP w0.114: R53.2 168.35,31.21 168.63,30.93 v1(168.63,30.3) 168.63,29.2 168.96,28.87 168.96,24.99 172.18,21.77 173.6,21.77 173.8,21.58 173.8,20.86 174.11,20.55 174.11,19.08 174.23,18.96 187.46,18.96 188.04,19.54 188.04,20.3 188.16,20.41 189.6,20.41 189.73,20.29 189.73,19.35 190.15,18.93 208.68,18.93 208.81,18.79 212.96,18.79 213.75,18 v1(213.75,17.94) v1(213.75,13.45)
  IN1 w0.127: v1(38.25,33.22) 40.15,35.13 146.12,35.13 151.93,29.32 166.88,29.32 167.85,30.3 v1(168.63,30.3)
  IN2 w0.127: J7.H5 222.22,11.15 221.65,11.71 215.48,11.71 v1(213.75,13.45)
  BOTTOM w0.114: v1(213.75,17.94) 213.75,18.39 214.38,19.03 214.38,32.9 224.08,42.6 224.08,52.79 222.95,53.91 J10.H5 222.95,54.52 224.66,56.23 227.16,56.23 232.19,61.26 232.19,66.59 225.8,72.97 225.8,84.72 224.05,86.48 224.05,95.39 222.95,96.49 J12.H5 ; v1(38.25,33.22) 37.96,33.22 36.48,31.75 30.81,31.75 24.79,37.76 17.13,37.76 14.85,40.04 8.04,40.04 4.16,43.91 4.16,53.51 3.67,54 J9.H5 3.92,54.97 3.92,56.21 6.2,58.49 9.65,59.92 11.94,62.21 11.94,67.77 4.15,75.55 4.15,95.88 3.18,96.85 J11.H5
SMB_SLED_BUF_SDA_R: length 5.4
  TOP w0.114: R51.2 R53.1 164.08,31.21 162.96,30.08 U118.3
SMB_SLED_COMBINE_SCL: length 202.4
  TOP w0.114: R46.1 152.19,29.94 v1(152.12,30.01) ; v1(35.59,30.63) 34.08,29.12 34.08,21.99 34.19,21.87 R1123.2 ; v1(177.31,35.75) 177.42,35.64 179.35,35.64 179.61,35.39 179.61,28.03 J8.G5
  IN1 w0.127: v1(35.59,30.63) 35.7,30.74 35.7,33.47 38.67,36.44 176.5,36.44 177.19,35.75 v1(177.31,35.75) 177.64,35.42 177.64,32.12 177.07,31.55 174.33,31.55 173.83,32.05 173.83,32.83 173.56,33.1 172.13,33.1 171.22,32.19 167.64,32.19 166.76,31.32 153.71,31.32 153.45,31.57 151.98,31.57 151.72,31.3 151.72,30.42 v1(152.12,30.01)
SMB_SLED_COMBINE_SCL_R: length 4.3
  TOP w0.114: U118.7 156.55,29.43 156.22,29.11 155.33,29.11 154.49,29.94 R46.2 R48.2
SMB_SLED_COMBINE_SDA: length 203.1
  TOP w0.114: R1122.2 33.9,20.75 33.41,21.23 33.41,29.51 v1(34.53,30.62) ; v1(177.71,36.25) 177.92,36.03 179.67,36.03 180,35.7 180,29.04 J8.H5 ; v1(152.32,30.99) 152.44,31.12 R47.1
  IN1 w0.127: v1(152.32,30.99) 153.37,29.94 166.23,29.94 167.23,30.94 170.43,30.94 171.15,30.23 177.36,30.23 178.16,31.03 178.16,35.79 v1(177.71,36.25) 177.49,36.46 177.09,36.46 176.68,36.87 38.47,36.87 35.22,33.62 35.22,31.31 v1(34.53,30.62)
SMB_SLED_COMBINE_SDA_R: length 4.5
  TOP w0.114: R49.2 R47.2 154.5,30.97 155.4,30.97 156.29,30.08 U118.6
TGND: length 7.2
  TOP w0.508: J22.3 v1(152.15,166.58) ; v1(90.54,104.84) 91.14,104.25 J34.3 ; J16.3 v1(152.15,128.74) ; J28.3 91.24,165.68 v1(91.83,165.08)
  BOTTOM w0.381: J27.3 v1(70.87,103.34) ; J33.3 v1(70.87,166.58)
  BOTTOM w0.508: J15.3 v1(131.83,166.58) ; J21.3 v1(131.83,128.74)
  vias: v1(64.94,177.03) v1(64.94,174.49) v1(64.94,171.95) v1(64.94,169.41) v1(64.94,166.87) v1(64.94,164.33) v1(64.94,161.79) v1(64.94,159.25) v1(64.94,156.71) v1(64.94,154.17) v1(64.94,151.63) v1(64.94,149.09) v1(64.94,146.55) v1(64.94,144.01) v1(64.94,141.47) v1(64.94,138.93) v1(64.94,136.39) v1(64.94,133.85) v1(64.94,131.31) v1(64.94,128.77) v1(64.94,126.23) v1(64.94,123.69) v1(64.94,121.15) v1(64.94,118.61) v1(64.94,116.07) v1(64.94,113.53) v1(64.94,110.99) v1(64.94,108.45) v1(64.94,105.91) v1(64.94,103.37) v1(64.94,100.83) v1(64.94,98.29) v1(64.94,95.75) v1(67.48,177.03) v1(67.48,95.75) v1(70.02,177.03) v1(70.02,95.75) v1(70.22,166.3) v1(70.22,165.08) v1(70.22,104.84) v1(70.22,103.62) v1(71.51,166.3) v1(71.51,165.08) v1(71.51,104.84) v1(71.51,103.62) v1(72.56,177.03) v1(72.56,95.75) v1(75.1,177.03) v1(75.1,95.75) v1(77.64,177.03) v1(77.64,95.75) v1(80.18,177.03) v1(80.18,95.75) v1(82.72,177.03) v1(82.72,95.75) v1(85.26,177.03) v1(85.26,95.75) v1(87.8,177.03) v1(87.8,95.75) v1(90.34,177.03) v1(90.34,95.75) v1(90.37,162.83) v1(90.41,107.07) v1(90.54,166.3) v1(90.54,165.08) v1(90.54,103.62) v1(91.19,166.58) v1(91.19,103.34) v1(91.83,166.3) v1(91.83,104.84) v1(91.83,103.62) v1(91.96,162.86) v1(92,107.09) v1(92.88,177.03) v1(92.88,95.75) v1(95.42,177.03) v1(95.42,95.75) v1(97.96,177.03) v1(97.96,95.75) v1(100.5,177.03) v1(100.5,95.75) v1(103.04,177.03) v1(103.04,95.75) v1(105.58,177.03) v1(105.58,95.75) v1(108.12,177.03) v1(108.12,95.75) v1(110.66,177.03) v1(110.66,95.75) v1(113.2,177.03) v1(113.2,95.75) v1(115.74,177.03) v1(115.74,95.75) v1(118.28,177.03) v1(118.28,95.75) v1(120.82,177.03) v1(120.82,95.75) v1(123.36,177.03) v1(123.36,95.75) v1(125.9,177.03) v1(125.9,95.75) v1(128.44,177.03) v1(128.44,121.15) v1(128.44,118.61) v1(128.44,116.07) v1(128.44,113.53) v1(128.44,110.99) v1(128.44,108.45) v1(128.44,105.91) v1(128.44,103.37) v1(128.44,100.83) v1(128.44,98.29) v1(128.44,95.75) v1(130.98,177.03) v1(130.98,121.15) v1(131.18,166.3) v1(131.18,165.08) v1(131.18,130.24) v1(131.18,129.02) v1(132.47,166.3) v1(132.47,165.08) v1(132.47,130.24) v1(132.47,129.02) v1(133.52,177.03) v1(133.52,121.15) v1(136.06,177.03) v1(136.06,121.15) v1(138.6,177.03) v1(138.6,121.15) v1(141.14,177.03) v1(141.14,121.15) v1(143.68,177.03) v1(143.68,121.15) v1(146.22,177.03) v1(146.22,121.15) v1(148.76,177.03) v1(148.76,121.15) v1(151.3,177.03) v1(151.33,162.83) v1(151.3,121.15) v1(151.37,132.47) v1(151.5,166.3) v1(151.5,165.08) v1(151.5,130.24) v1(151.5,129.02) v1(152.79,166.3) v1(152.79,165.08) v1(152.79,130.24) v1(152.79,129.02) v1(152.92,162.86) v1(152.96,132.49) v1(153.84,177.03) v1(153.84,121.15) v1(156.38,177.03) v1(156.38,121.15) v1(158.92,177.03) v1(158.92,121.15) v1(161.46,177.03) v1(161.46,121.15) v1(164,177.03) v1(164,121.15) v1(166.54,177.03) v1(166.54,121.15) v1(169.08,177.03) v1(169.08,121.15) v1(171.62,177.03) v1(171.62,121.15) v1(174.16,177.03) v1(174.16,121.15) v1(176.7,177.03) v1(176.7,121.15) v1(179.24,177.03) v1(179.24,174.49) v1(179.24,171.95) v1(179.24,169.41) v1(179.24,166.87) v1(179.24,164.33) v1(179.24,161.79) v1(179.24,159.25) v1(179.24,156.71) v1(179.24,154.17) v1(179.24,151.63) v1(179.24,149.09) v1(179.24,146.55) v1(179.24,144.01) v1(179.24,141.47) v1(179.24,138.93) v1(179.24,136.39) v1(179.24,133.85) v1(179.24,131.31) v1(179.24,128.77) v1(179.24,126.23) v1(179.24,123.69) v1(179.24,121.15)
TMP75_1_A0: length 5.9
  TOP w0.114: R1113.2 R1114.1 37.84,28.28 v2(38.13,27.98) 38.91,27.21 U31.7
TMP75_1_A1: length 5.4
  TOP w0.114: U31.6 v2(40.18,27.72) 40.18,29.69 R1108.2 R1109.1
TMP75_1_A2: length 6.2
  TOP w0.114: U31.5 41.45,26.7 42.31,27.57 42.31,28.17 41.45,29.04 41.45,29.55 R1102.2 R1103.1
TP_BUF_EN: length 4.6
  TOP w0.114: 154.42,33.64 154.75,33.64 155.29,33.1 155.29,32.01 156.49,30.81 U118.5
TP_TMP75_1_ALERT: length 2.2
  TOP w0.114: 40.98,18.14 40.18,18.95 U31.3

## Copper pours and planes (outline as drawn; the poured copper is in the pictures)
GND on TOP (solid shape): 1.02,66.99 0.51,66.99 0.51,86.32 1.02,86.32
GND on TOP (solid shape): 244.9,1 236.9,1 236.9,3 244.9,3
GND on TOP (solid shape): 149.84,16.54 149.33,16.54 149.33,16.75 116.9,16.75 116.9,17.26 149.84,17.26
GND on TOP (solid shape): 11.89,80.37 11.89,79.3 11.84,79.25 10.34,79.25 10.24,79.35 10.24,80.37 10.29,80.42 11.84,80.42
GND on TOP (solid shape): 230.58,79.98 230.58,78.92 230.53,78.87 229.03,78.87 228.93,78.97 228.93,79.98 228.98,80.04 230.53,80.04
GND on TOP (solid shape): 255.82,25.62 256.43,25.02 256.43,3.58 255.84,2.99 249.83,2.99 249.54,3.28 249.54,25.01 250.17,25.64 255.82,25.64
GND on TOP (solid shape): 36.08,65.24 36.58,65.24 36.79,65.02 36.79,47.64 36.62,47.46 32.37,47.46 31.75,48.08 31.75,64.66 32.33,65.24 36.08,65.24
GND on TOP (solid shape): 36.39,110.97 36.44,110.97 36.48,110.93 36.48,84.51 36.47,84.51 36.47,84.02 35.59,83.14 31.85,83.14 31.75,83.24 31.75,109.88 33.23,111.36 36.01,111.36
GND on TOP (solid shape): 256.99,1 256.85,0.65 256.5,0.51 232.2,0.51 232.2,1.02 256.48,1.02 256.48,3.14 256.99,3.14
GND on TOP (solid shape): 149.84,9.74 152.3,9.74 152.6,9.71 152.9,9.7 156.4,9.7 156.7,9.71 157,9.74 160.9,9.74 160.9,9.23 149.82,9.23 149.48,9.38 149.33,9.72 149.33,10.85 149.84,10.85
GND on TOP (solid shape): 96.33,11.5 96.41,11.6 96.52,11.55 96.67,11.33 96.84,11.12 96.84,9.74 99.3,9.74 99.6,9.71 99.9,9.7 103.4,9.7 103.7,9.71 104,9.74 107.9,9.74 107.9,9.23 96.83,9.23 96.48,9.38 96.33,9.72
GND on TOP (solid shape): 194.87,9.74 202.3,9.74 202.6,9.71 202.9,9.7 206.4,9.7 206.7,9.71 207,9.74 219,9.74 219.3,9.72 219.58,9.65 219.58,9.26 219.54,9.18 219.45,9.16 219.23,9.22 219,9.23 194.85,9.23 194.5,9.38 194.36,9.72 194.36,16.74 169.9,16.74 169.9,17.25 194.87,17.25
GND on TOP (solid shape): 1.02,39.15 26.58,13.58 26.57,13.55 26.6,13.35 26.8,13.31 26.83,13.33 30.42,9.74 35.3,9.74 35.6,9.71 35.9,9.7 39.4,9.7 39.7,9.71 40,9.74 44.96,9.74 44.96,17.26 96.84,17.26 96.84,16.28 96.83,16.27 96.67,16.06 96.52,15.85 96.41,15.8 96.33,15.9 96.33,16.75 45.47,16.75 45.47,9.72 45.32,9.38 44.98,9.23 30.41,9.23 30.23,9.27 30.07,9.38 0.65,38.79 0.55,38.95 0.51,39.14 0.51,42.17 1.02,42.17
GND on TOP (solid shape): 256.33,110.83 256.33,110.83 256.33,83.59 255.94,83.19 254.49,83.19 254.27,82.97 254.25,82.97 253.53,82.57 253.13,81.85 253.13,81.83 253.03,81.73 253.03,69.41 253.76,68.67 255.45,68.67 255.45,68.67 256.43,67.69 256.43,40.97 255.93,40.47 249.63,40.47 249.63,72.37 251.4,75.7 249.63,79.03 249.63,111.35 249.67,111.4 255.76,111.4
GND on TOP (solid shape): 164.76,36.95 164.76,33.87 164.59,33.69 162,33.69 161.87,33.81 156.71,33.81 156.56,33.96 156.56,34.66 156.54,34.66 156.54,35.29 156.56,35.29 156.56,36.05 156.54,36.05 156.54,36.13 156.41,36.27 152.53,36.27 151.95,35.68 151.95,34.98 150.16,33.19 150.13,33.2 149.63,32.69 150.35,32.77 150.35,32.79 150.86,33.29 150.97,33.32 151.03,33.22 151.03,33.01 151.24,32.31 151.45,33.01 151.45,33.2 151.78,33.52 151.89,33.55 151.95,33.45 151.95,31.11 151.95,31.1 151.93,30.99 151.95,30.89 151.95,30.88 151.95,30.35 151.74,30.01 151.95,29.67 151.95,18.97 151.08,18.09 144.08,18.09 144.01,18.16 144.01,37.47 150.69,37.47 150.93,37.7 164,37.7
GND on TOP (solid shape): 32.6,114.49 32.95,114.35 33.09,114 33.09,113.1 33.53,112.03 34.6,111.59 36.5,111.59 36.85,111.45 36.99,111.1 36.99,83.5 36.85,83.15 36.5,83.01 34.6,83.01 33.53,82.57 33.09,81.5 33.09,70.25 33.53,69.18 34.6,68.74 36.5,68.74 36.85,68.6 36.99,68.25 36.99,40.85 37.43,39.78 38.5,39.34 213,39.34 214.07,39.78 214.51,40.85 214.51,114 214.65,114.35 215,114.49 252.6,114.49 252.95,114.35 253.09,114 253.09,113.1 253.11,112.84 253.18,112.59 253.17,112.5 253.09,112.45 252.69,112.45 252.61,112.77 252.58,113.1 252.58,113.98 215.02,113.98 215.02,40.85 214.43,39.42 213,38.83 38.5,38.83 37.07,39.42 36.48,40.85 36.48,68.23 34.6,68.23 33.17,68.82 32.58,70.25 32.58,81.5 33.17,82.93 34.6,83.52 36.48,83.52 36.48,111.08 34.6,111.08 33.17,111.67 32.58,113.1 32.58,113.98 1.02,113.98 1.02,109.83 0.97,109.78 0.51,109.78 0.51,114 0.65,114.35 1,114.49
GND on BOTTOM (solid shape): 1.02,67 0.51,67 0.51,84.77 1.02,84.77
GND on BOTTOM (solid shape): 244.9,1 236.9,1 236.9,3 244.9,3
GND on BOTTOM (solid shape): 149.84,16.28 149.83,16.27 149.67,16.06 149.52,15.85 149.41,15.8 149.33,15.9 149.33,16.75 116.9,16.75 116.9,17.26 149.84,17.26
GND on BOTTOM (solid shape): 96.33,11.5 96.41,11.6 96.52,11.55 96.67,11.33 96.84,11.12 96.84,9.74 99.3,9.74 99.6,9.71 99.9,9.7 103.4,9.7 103.7,9.71 104,9.74 107.9,9.74 107.9,9.23 96.83,9.23 96.48,9.38 96.33,9.72
GND on BOTTOM (solid shape): 149.33,11.5 149.41,11.6 149.52,11.55 149.67,11.33 149.84,11.12 149.84,9.74 152.3,9.74 152.6,9.71 152.9,9.7 156.4,9.7 156.7,9.71 157,9.74 160.9,9.74 160.9,9.23 149.82,9.23 149.48,9.38 149.33,9.72
GND on BOTTOM (solid shape): 1.02,39.15 30.42,9.74 35.3,9.74 35.6,9.71 35.9,9.7 39.4,9.7 39.7,9.71 40,9.74 44.96,9.74 44.96,17.26 96.84,17.26 96.84,16.28 96.83,16.27 96.67,16.06 96.52,15.85 96.41,15.8 96.33,15.9 96.33,16.75 45.47,16.75 45.47,9.72 45.32,9.38 44.98,9.23 30.41,9.23 30.23,9.27 30.07,9.38 0.65,38.79 0.55,38.95 0.51,39.14 0.51,42.17 1.02,42.17
GND on BOTTOM (solid shape): 189.87,17.12 190.29,16.95 192.26,16.95 192.99,17.25 194.87,17.25 194.87,9.74 202.3,9.74 202.6,9.71 202.9,9.7 206.4,9.7 206.7,9.71 207,9.74 219,9.74 219.58,9.65 220.11,9.4 220.11,8.98 220.06,8.88 219.95,8.9 219.5,9.15 219,9.23 194.85,9.23 194.5,9.38 194.36,9.72 194.36,16.74 169.9,16.74 169.9,17.25 189.74,17.25
GND on BOTTOM (solid shape): 252.88,113.94 252.88,113.14 252.9,113.14 252.94,113.11 252.93,113.06 252.88,113 252.88,112.4 253.85,111.42 253.87,111.42 253.94,111.36 253.94,111.36 256.42,108.88 256.42,84.36 255.34,83.28 253.87,83.28 252.93,82.35 252.93,81.91 252.96,81.88 252.96,70.62 252.9,70.55 252.9,69.65 253.87,68.68 253.89,68.67 256.45,66.12 256.45,40.72 256.16,40.44 253.9,40.44 253.03,39.56 253.03,25.56 255.36,25.56 255.36,25.55 256.48,24.42 256.48,2.07 255.47,1.06 251.04,1.06 250.64,1.46 250.64,3.67 250.65,3.69 250.65,20.54 250.82,20.7 250.82,28.89 252.7,32.8 250.82,36.71 250.82,73.62 251.4,75.7 250.82,77.78 250.82,110.49 250.97,110.64 250.97,111.25 250.62,111.61 232.96,111.61 232.95,111.62 217.08,111.62 216.38,110.92 216.38,62.77 216.34,41.86 215.62,41.15 214.68,41.15 214.61,41.22 214.61,113.95 214.91,114.25 252.56,114.25
GND on BOTTOM (solid shape): 252.6,114.49 252.95,114.35 253.09,114 253.09,113.1 253.53,112.03 254.6,111.59 255.42,111.59 255.42,111.08 254.6,111.08 253.17,111.67 252.58,113.1 252.58,113.98 215.02,113.98 215.02,40.85 214.43,39.42 213,38.83 177.99,38.83 177.9,38.92 38.58,38.92 38.33,39.17 38.31,39.28 38.41,39.34 38.5,39.34 213,39.34 214.07,39.78 214.51,40.85 214.51,114 214.65,114.35 215,114.49
GND on BOTTOM (solid shape): 32.6,114.49 32.95,114.35 33.09,114 33.09,113.1 33.53,112.03 34.6,111.59 36.5,111.59 36.85,111.45 36.99,111.1 36.99,83.5 36.85,83.15 36.5,83.01 34.6,83.01 33.53,82.57 33.09,81.5 33.09,70.25 33.53,69.18 34.6,68.74 36.5,68.74 36.85,68.6 36.99,68.25 36.99,40.85 36.99,40.76 36.93,40.66 36.82,40.68 36.48,41.02 36.48,68.23 34.6,68.23 33.17,68.82 32.58,70.25 32.58,81.5 33.17,82.93 34.6,83.52 36.48,83.52 36.48,111.08 34.6,111.08 33.17,111.67 32.58,113.1 32.58,113.98 1.02,113.98 1.02,109.84 0.51,109.84 0.51,114 0.65,114.35 1,114.49
GND on BOTTOM (solid shape): outline of 1286 points within 11.79,83.16 36.37,114.4
GND on BOTTOM (solid shape): outline of 2865 points within 16.1,10.83 160.6,36.39
GND on GND (solid shape): outline of 3510 points within 0.51,0.51 256.99,114.49
GND on IN1 (solid shape): 149.84,9.74 165.33,9.74 165.33,9.23 149.82,9.23 149.48,9.38 149.33,9.72 149.33,16.75 116.47,16.75 116.47,10.73 115.96,10.73 115.96,17.26 149.84,17.26
GND on IN1 (solid shape): 194.87,9.74 219,9.74 219.66,9.63 220.25,9.31 220.25,8.86 220.18,8.76 220.07,8.79 219.58,9.12 219,9.23 194.85,9.23 194.5,9.38 194.36,9.72 194.36,16.74 169.44,16.74 169.44,12.05 168.93,12.05 168.93,17.04 169,17.14 169.11,17.11 169.35,16.87 191.95,16.87 192.34,17.25 194.87,17.25
GND on IN1 (solid shape): 0.51,44.97 0.56,45.06 0.66,45.05 0.79,45 0.92,44.97 0.99,44.94 1.02,44.87 1.02,39.15 30.42,9.74 44.96,9.74 44.96,17.26 96.84,17.26 96.84,9.74 112.47,9.74 112.6,9.57 112.76,9.41 112.79,9.3 112.69,9.23 96.83,9.23 96.48,9.38 96.33,9.72 96.33,16.75 45.47,16.75 45.47,9.72 45.32,9.38 44.98,9.23 30.41,9.23 30.23,9.27 30.07,9.38 0.65,38.79 0.55,38.95 0.51,39.14
GND on IN1 (solid shape): 32.6,114.49 32.95,114.35 33.09,114 33.09,113.1 33.53,112.03 34.6,111.59 36.5,111.59 36.85,111.45 36.99,111.1 36.99,83.5 36.85,83.15 36.5,83.01 34.6,83.01 33.53,82.57 33.09,81.5 33.09,70.25 33.53,69.18 34.6,68.74 36.5,68.74 36.85,68.6 36.99,68.25 36.99,40.85 37.43,39.78 38.5,39.34 213,39.34 214.07,39.78 214.51,40.85 214.51,114 214.65,114.35 215,114.49 252.6,114.49 252.95,114.35 253.09,114 253.09,113.57 252.58,113.57 252.58,113.98 215.02,113.98 215.02,40.85 214.43,39.42 213,38.83 38.48,38.83 37.07,39.43 36.48,40.85 36.48,68.23 34.6,68.23 33.17,68.82 32.58,70.25 32.58,81.5 33.17,82.93 34.6,83.52 36.48,83.52 36.48,111.08 34.6,111.08 33.17,111.67 32.58,113.1 32.58,113.98 1.02,113.98 1.02,98.78 0.99,98.71 0.92,98.68 0.79,98.66 0.66,98.6 0.56,98.59 0.51,98.68 0.51,114 0.65,114.35 1,114.49
GND on IN1 (solid shape): outline of 4321 points within 0.64,9.45 44.89,114.37
GND on IN1 (solid shape): outline of 5639 points within 194.54,0.64 256.47,114.25
GND on IN2 (solid shape): 1.02,56.21 0.51,56.21 0.51,86.19 1.02,86.19
GND on IN2 (solid shape): 149.84,9.74 165.46,9.74 165.6,9.57 165.76,9.41 165.79,9.3 165.69,9.23 149.82,9.23 149.48,9.38 149.33,9.72 149.33,16.75 116.47,16.75 116.47,11.19 115.96,11.19 115.96,17.26 149.84,17.26
GND on IN2 (solid shape): 190.12,16.86 191.32,16.86 192.25,17.25 194.87,17.25 194.87,9.74 219,9.74 219.59,9.65 220.13,9.39 220.13,8.96 220.07,8.87 219.96,8.89 219.51,9.14 219,9.23 194.85,9.23 194.5,9.38 194.36,9.72 194.36,16.74 169.44,16.74 169.44,10.42 168.93,10.42 168.93,17.25 189.74,17.25
GND on IN2 (solid shape): 1.02,39.15 30.42,9.74 44.96,9.74 44.96,17.26 96.84,17.26 96.84,9.74 112.47,9.74 112.6,9.57 112.76,9.41 112.79,9.3 112.69,9.23 96.83,9.23 96.48,9.38 96.33,9.72 96.33,16.75 45.47,16.75 45.47,9.72 45.32,9.38 44.98,9.23 30.41,9.23 30.23,9.27 30.07,9.38 0.65,38.79 0.55,38.95 0.51,39.14 0.51,43.32 1.02,43.32
